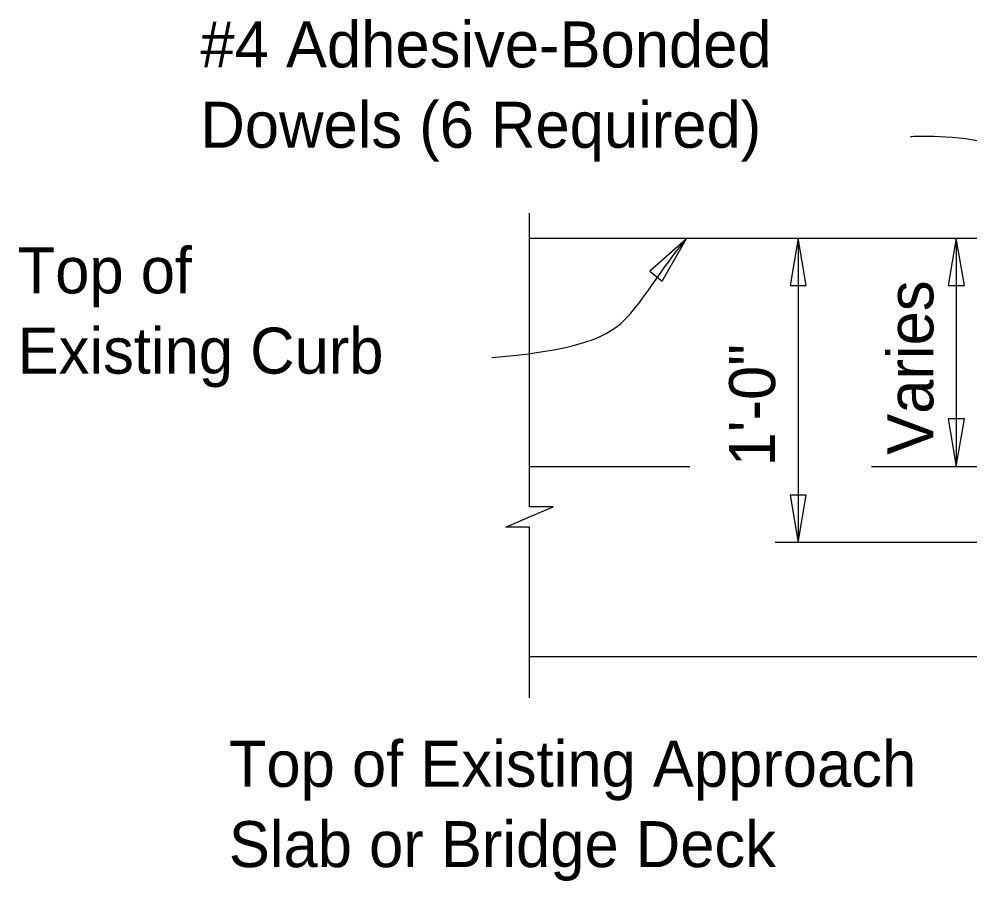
# Model space of a CAD drawing. Extents: x 0 to 120, y 0 to 45.
# Drawn here: x 5.19 to 11.44, y 18.24 to 23.9 of the extents above; entities that cross this region are included whole.
import ezdxf

# ---------------------------------------------------------------- set-up
doc = ezdxf.new("R2010")
doc.units = 0
for name, color, linetype in [('AdhocPoint_dp', 7, 'Continuous'), ('PlotBorder_dp', 7, 'Continuous'), ('TextStructures', 7, 'Continuous')]:
    doc.layers.add(name, color=color, linetype=linetype)

# ---------------------------------------------------------------- blocks, each defined once
blk = doc.blocks.new('Terminator-Arrow')
at = {"layer": 'PlotBorder_dp'}
blk.add_lwpolyline([(0, 0), (-0.0004099, 0.0000694), (-0.0004099, -0.0000694)], close=True, dxfattribs=at)

msp = doc.modelspace()

# ---------------------------------------------------------------- linework, layer by layer
at = {"layer": 'AdhocPoint_dp'}
for p, q in [((8.5421, 22.4627), (13.8798, 22.4627)), ((8.5421, 20.9627), (9.5946, 20.9627)), ((10.7906, 20.9627), (13.8798, 20.9627)), ((8.5421, 19.7129), (14.9846, 19.7129))]:
    msp.add_line(p, q, dxfattribs=at)
at = {"layer": 'PlotBorder_dp'}
for p, q in [((10.3076, 22.4627), (10.3076, 20.4629)), ((11.3473, 22.4627), (11.3473, 20.9627)), ((13.7286, 20.4629), (10.1564, 20.4629))]:
    msp.add_line(p, q, dxfattribs=at)
msp.add_lwpolyline([(8.5421, 19.4402), (8.5421, 20.5626), (8.3871, 20.5626), (8.5421, 20.6301), (8.6971, 20.6976), (8.5421, 20.6976), (8.5421, 22.6288)], dxfattribs=at)
for points in [[(9.5706, 22.4559), (9.3323, 22.2472), (9.4143, 22.1803)], [(11.3473, 20.9627), (11.4002, 21.2751), (11.2944, 21.2751)]]:
    msp.add_lwpolyline(points, close=True, dxfattribs=at)
for points in [[(11.047, 23.1328), (11.0771, 23.1328), (11.607, 23.1672), (12.3848, 22.698), (12.6772, 22.3209), (12.9013, 22.0892), (13.3989, 21.5102), (13.586, 21.274)], [(8.2942, 21.6791), (8.9586, 21.7328), (9.2393, 21.955), (9.3932, 22.2382), (9.5706, 22.456)]]:
    msp.add_open_spline(points, degree=3, dxfattribs=at)

# ---------------------------------------------------------------- block references
at = {"layer": 'PlotBorder_dp', "xscale": 759.4584810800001, "yscale": 768.046082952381}
for p, rotation in [((10.3074, 22.4627), 90), ((11.3471, 22.4627), 90), ((10.3074, 20.4628), -90)]:
    msp.add_blockref('Terminator-Arrow', p, dxfattribs=dict(at, rotation=rotation))

# ---------------------------------------------------------------- texts
at = {"layer": 'TextStructures'}
for s, height, p in [('#4 Adhesive-Bonded ', 0.302401, (6.3788, 23.5861)), ('Dowels (6 Required)', 0.302401, (6.3788, 23.0581)), ('Top of ', 0.3024, (5.1773, 22.1007)), ('Existing Curb', 0.302401, (5.1773, 21.5727)), ('Top of Existing Approach ', 0.302401, (6.5655, 18.8559)), ('Slab or Bridge Deck', 0.302401, (6.5655, 18.3279))]:
    msp.add_text(s, height=height, dxfattribs=at).set_placement(p)
for s, p in [('Varies', (11.196, 21.0393)), ('1\'-0"', (10.1563, 20.9628))]:
    msp.add_text(s, height=0.3024, rotation=90, dxfattribs=at).set_placement(p)

doc.saveas('drawing.dxf')
